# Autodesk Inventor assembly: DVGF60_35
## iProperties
Created: 2010-04
Part Number: DVGF60_35
Document SubType Name: Assembly
Designer: TB
Mass: 1032.96 g
Surface Area: 1720.55 cm^2
Volume: 1032.96 cm^3
Density: 1 g/cm^3
Description: KM DVGF 60/35 - 100 mm
Slaglengde: 100.000 mm
Author: TB
